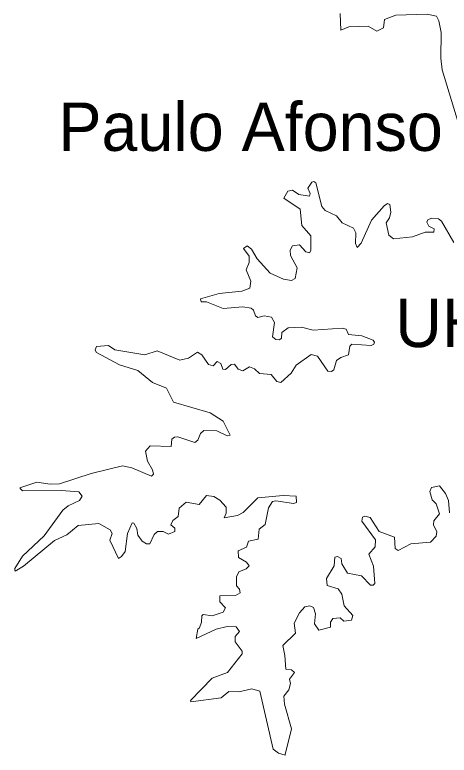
# Model space of a CAD drawing. Extents: x 553962 to 842807, y 8883888 to 9032388.
# Drawn here: x 579268 to 583762, y 8954217 to 8961876 of the extents above; entities that cross this region are included whole.
import ezdxf
from ezdxf.enums import TextEntityAlignment as Align

# ---------------------------------------------------------------- set-up
doc = ezdxf.new("R2010")
doc.units = 0
doc.header["$LTSCALE"] = 200
doc.layers.add('25', color=7, linetype='Continuous', lineweight=13)
doc.layers.add('41', color=7, linetype='Continuous')
doc.layers.add('42', color=7, linetype='Continuous')

msp = doc.modelspace()

# ---------------------------------------------------------------- linework, layer by layer
at = {"layer": '25'}
for points in [[(583979.3, 8960356.6), (583690.5, 8961308.2), (583675.7, 8961427), (583679.9, 8961694.8), (583656.7, 8961812.9), (583631.9, 8961861.4), (583535.2, 8961883.6), (583208.6, 8961873.1), (583093.8, 8961826.3), (583082.9, 8961741.4), (583013.1, 8961707.5), (582923.6, 8961760.4), (582724.2, 8961752), (582642.1, 8961718.4), (582632.6, 8961889.8)], [(583979.3, 8960356.6), (583690.5, 8961308.2), (583675.7, 8961427), (583679.9, 8961694.8), (583656.7, 8961812.9), (583631.9, 8961861.4), (583535.2, 8961883.6), (583208.6, 8961873.1), (583093.8, 8961826.3), (583082.9, 8961741.4), (583013.1, 8961707.5), (582923.6, 8961760.4), (582724.2, 8961752), (582642.1, 8961718.4), (582632.6, 8961889.8)], [(582299.4, 8960082.5), (582339.6, 8960143.8), (582362.8, 8960152.2), (582381.9, 8960139.6), (582443.6, 8959893.3), (582477.6, 8959853), (582596.3, 8959797.7), (582656.1, 8959725.5), (582771.8, 8959670.2), (582795.6, 8959619.4), (582792, 8959510.9), (582809, 8959470.7), (582851.4, 8959515.1), (582957.8, 8959753.2), (583089.5, 8959901.9), (583125.3, 8959922.9), (583148.8, 8959914.2), (583159.4, 8959833.8), (583144.6, 8959774.5), (583108.6, 8959723.3), (583108.6, 8959723.3), (583138.3, 8959595.9), (583184.5, 8959559.9), (583382, 8959578.8), (583514.4, 8959627.7), (583603.4, 8959628), (583607.5, 8959661.8), (583550.2, 8959691.6), (583531.3, 8959731.8), (583541.6, 8959757), (583580.3, 8959774.3), (583651.7, 8959765.9), (583684, 8959740.2), (583809.5, 8959521.5)], [(582299.4, 8960082.5), (582339.6, 8960143.8), (582362.8, 8960152.2), (582381.9, 8960139.6), (582443.6, 8959893.3), (582477.6, 8959853), (582596.3, 8959797.7), (582656.1, 8959725.5), (582771.8, 8959670.2), (582795.6, 8959619.4), (582792, 8959510.9), (582809, 8959470.7), (582851.4, 8959515.1), (582957.8, 8959753.2), (583089.5, 8959901.9), (583125.3, 8959922.9), (583148.8, 8959914.2), (583159.4, 8959833.8), (583144.6, 8959774.5), (583108.6, 8959723.3), (583108.6, 8959723.3), (583138.3, 8959595.9), (583184.5, 8959559.9), (583382, 8959578.8), (583514.4, 8959627.7), (583603.4, 8959628), (583607.5, 8959661.8), (583550.2, 8959691.6), (583531.3, 8959731.8), (583541.6, 8959757), (583580.3, 8959774.3), (583651.7, 8959765.9), (583684, 8959740.2), (583809.5, 8959521.5)], [(580099.6, 8958407.9), (580098.5, 8958410.3), (580113.2, 8958444.3), (580235.9, 8958453.9), (580303, 8958410.4), (580612.5, 8958359.6), (580740.2, 8958401.9), (580973.9, 8958304.4), (581064.7, 8958323.4), (581156.5, 8958384.9), (581203.2, 8958359.3), (581270.9, 8958257.8), (581319.8, 8958245), (581360.2, 8958291.4), (581400.5, 8958268.1), (581420.4, 8958210.8), (581447.3, 8958208.8), (581504.7, 8958259.6), (581539.6, 8958263.8), (581539.6, 8958263.8), (581578.9, 8958209), (581627.9, 8958191.9), (581696, 8958236.1), (581748.9, 8958212.8), (581799.4, 8958164.3), (581920, 8958154), (581978.5, 8958081.4), (582019.4, 8958072.8), (582127.2, 8958170.8), (582178.1, 8958253.3), (582332.9, 8958361.5), (582401, 8958344.6), (582505.1, 8958189.8), (582543.4, 8958185.4), (582568.8, 8958204.3), (582596.6, 8958300), (582641.2, 8958331.9), (582721.7, 8958357.6), (582732.5, 8958448.5), (582755.7, 8958467.7), (582953.2, 8958455.2), (582983.1, 8958470.1), (582989.4, 8958491.2), (582974.4, 8958510.4), (582859.9, 8958554.9), (582719.7, 8958570.1), (582696.2, 8958625.2), (582656.2, 8958635.6), (582353.6, 8958614.5), (582235.7, 8958646.3), (582095.5, 8958639.9), (582031.7, 8958591.2), (582027, 8958531.6), (582005.7, 8958514.7), (581967.3, 8958516.9), (581933.7, 8958544.9), (581955, 8958692.5), (581922.9, 8958748.3), (581848.8, 8958761), (581780.6, 8958746.3), (581757.5, 8958761.1), (581738.2, 8958822.6), (581712.6, 8958841.7), (581627.9, 8958854.5), (581424.2, 8958839.7), (581251.8, 8958907.5), (581194.6, 8958907.9), (581190.6, 8958937.3), (581381.2, 8958994.6), (581615.1, 8959015.9), (581699.9, 8959047.7), (581708.6, 8959122.1), (581659.8, 8959239), (581692.1, 8959315.5), (581691.6, 8959378.9), (581634.5, 8959460), (581670.4, 8959485.2), (581717.2, 8959451.2), (581774.6, 8959353.5), (581908.3, 8959202.9), (582046.5, 8959141.3), (582129.4, 8959128.6), (582167.3, 8959147.5), (582188.6, 8959260.2), (582118.7, 8959385.4), (582116.5, 8959440.5), (582142.1, 8959487.4), (582214.1, 8959495.9), (582278, 8959423.9), (582316.1, 8959415.5), (582331, 8959439.1), (582330.8, 8959589.7), (582237.6, 8959695.7), (582220.4, 8959865.6), (582050.7, 8959980.4), (582091.2, 8960052.6), (582141.7, 8960063.2), (582208.1, 8960016.5), (582315.9, 8960001.7), (582322.5, 8960029), (582299.4, 8960082.5)], [(580099.6, 8958407.9), (580098.5, 8958410.3), (580113.2, 8958444.3), (580235.9, 8958453.9), (580303, 8958410.4), (580612.5, 8958359.6), (580740.2, 8958401.9), (580973.9, 8958304.4), (581064.7, 8958323.4), (581156.5, 8958384.9), (581203.2, 8958359.3), (581270.9, 8958257.8), (581319.8, 8958245), (581360.2, 8958291.4), (581400.5, 8958268.1), (581420.4, 8958210.8), (581447.3, 8958208.8), (581504.7, 8958259.6), (581539.6, 8958263.8), (581539.6, 8958263.8), (581578.9, 8958209), (581627.9, 8958191.9), (581696, 8958236.1), (581748.9, 8958212.8), (581799.4, 8958164.3), (581920, 8958154), (581978.5, 8958081.4), (582019.4, 8958072.8), (582127.2, 8958170.8), (582178.1, 8958253.3), (582332.9, 8958361.5), (582401, 8958344.6), (582505.1, 8958189.8), (582543.4, 8958185.4), (582568.8, 8958204.3), (582596.6, 8958300), (582641.2, 8958331.9), (582721.7, 8958357.6), (582732.5, 8958448.5), (582755.7, 8958467.7), (582953.2, 8958455.2), (582983.1, 8958470.1), (582989.4, 8958491.2), (582974.4, 8958510.4), (582859.9, 8958554.9), (582719.7, 8958570.1), (582696.2, 8958625.2), (582656.2, 8958635.6), (582353.6, 8958614.5), (582235.7, 8958646.3), (582095.5, 8958639.9), (582031.7, 8958591.2), (582027, 8958531.6), (582005.7, 8958514.7), (581967.3, 8958516.9), (581933.7, 8958544.9), (581955, 8958692.5), (581922.9, 8958748.3), (581848.8, 8958761), (581780.6, 8958746.3), (581757.5, 8958761.1), (581738.2, 8958822.6), (581712.6, 8958841.7), (581627.9, 8958854.5), (581424.2, 8958839.7), (581251.8, 8958907.5), (581194.6, 8958907.9), (581190.6, 8958937.3), (581381.2, 8958994.6), (581615.1, 8959015.9), (581699.9, 8959047.7), (581708.6, 8959122.1), (581659.8, 8959239), (581692.1, 8959315.5), (581691.6, 8959378.9), (581634.5, 8959460), (581670.4, 8959485.2), (581717.2, 8959451.2), (581774.6, 8959353.5), (581908.3, 8959202.9), (582046.5, 8959141.3), (582129.4, 8959128.6), (582167.3, 8959147.5), (582188.6, 8959260.2), (582118.7, 8959385.4), (582116.5, 8959440.5), (582142.1, 8959487.4), (582214.1, 8959495.9), (582278, 8959423.9), (582316.1, 8959415.5), (582331, 8959439.1), (582330.8, 8959589.7), (582237.6, 8959695.7), (582220.4, 8959865.6), (582050.7, 8959980.4), (582091.2, 8960052.6), (582141.7, 8960063.2), (582208.1, 8960016.5), (582315.9, 8960001.7), (582322.5, 8960029), (582299.4, 8960082.5)], [(579330.4, 8956970.9), (579320.1, 8956982.2), (579494.9, 8957040.3), (579635.1, 8957021.3), (579729, 8957025.6), (580056.8, 8957131.9), (580383.3, 8957210.3), (580477.4, 8957190.9), (580682.8, 8957104.2), (580701.6, 8957122.8), (580693.2, 8957169.7), (580640, 8957259.4), (580619.2, 8957363.6), (580667.8, 8957416.2), (580886.3, 8957410), (580890.9, 8957486.6), (580919.1, 8957507.7), (580955.2, 8957509.6), (581130.8, 8957450.5), (581162.8, 8957476.1), (581188.5, 8957544.2), (581224.5, 8957577.8), (581357.9, 8957571.4), (581466.2, 8957520.6), (581496, 8957526.9), (581421.8, 8957673.3), (581289.9, 8957760.6), (580910.1, 8957870.9), (580835.5, 8958013.2), (580692.5, 8958073.2), (580540.2, 8958198), (580349.1, 8958255.5), (580111.4, 8958382.8), (580099.6, 8958407.9)], [(579330.4, 8956970.9), (579320.1, 8956982.2), (579494.9, 8957040.3), (579635.1, 8957021.3), (579729, 8957025.6), (580056.8, 8957131.9), (580383.3, 8957210.3), (580477.4, 8957190.9), (580682.8, 8957104.2), (580701.6, 8957122.8), (580693.2, 8957169.7), (580640, 8957259.4), (580619.2, 8957363.6), (580667.8, 8957416.2), (580886.3, 8957410), (580890.9, 8957486.6), (580919.1, 8957507.7), (580955.2, 8957509.6), (581130.8, 8957450.5), (581162.8, 8957476.1), (581188.5, 8957544.2), (581224.5, 8957577.8), (581357.9, 8957571.4), (581466.2, 8957520.6), (581496, 8957526.9), (581421.8, 8957673.3), (581289.9, 8957760.6), (580910.1, 8957870.9), (580835.5, 8958013.2), (580692.5, 8958073.2), (580540.2, 8958198), (580349.1, 8958255.5), (580111.4, 8958382.8), (580099.6, 8958407.9)], [(583767, 8956723.9), (583756.3, 8956851.3), (583724.4, 8956925.6), (583660.8, 8957002.1), (583580.2, 8956987.2), (583561.1, 8956946.9), (583586.5, 8956859.9), (583628.7, 8956817.4), (583660.7, 8956715.7), (583603.4, 8956642.9), (583599.3, 8956600.4), (583635.2, 8956528.2), (583628.9, 8956482), (583569.2, 8956422.2), (583365.5, 8956403), (583235.8, 8956333.2), (583204.2, 8956354.3), (583197.6, 8956473.1), (583036.3, 8956532.7), (582944.7, 8956675), (582889.9, 8956689.8), (582866.4, 8956681.3), (582857.8, 8956639.1), (583000.1, 8956445.4), (583000.1, 8956445.4), (582995.8, 8956371.3), (582932.2, 8956297.6), (582978.9, 8956171.6), (582991.4, 8955993), (582976.7, 8955976.2), (582947.1, 8955976.2), (582856.3, 8956071.3), (582711.3, 8956099.4), (582652.2, 8956196.2), (582645.2, 8956252.4), (582607.4, 8956273.4), (582579.8, 8956265), (582570.9, 8956175.6), (582492.5, 8956044.1), (582498.8, 8955974.4), (582613.2, 8955937.9), (582649.7, 8955884.6), (582675.3, 8955763.5), (582766.3, 8955661.9), (582751.6, 8955613.2), (582671.6, 8955604.4), (582632.4, 8955638.4), (582558.3, 8955632), (582532.9, 8955594), (582534.7, 8955540.7), (582411.8, 8955511), (582367.2, 8955576.8), (582379.8, 8955678.5), (582358.6, 8955744.6), (582321.7, 8955763.6), (582269.6, 8955750.9), (582214, 8955691.2), (582157.1, 8955581.8), (582171.5, 8955478.9), (582040.1, 8955351.6), (582061.2, 8955249.4), (582072.2, 8955107.3), (582129.2, 8955100.8), (582163, 8955071.2), (582108.2, 8955005.5), (582120.6, 8954960.7), (582103.7, 8954893.1), (582052.8, 8954828.8), (582057, 8954744.1), (582129.2, 8954489.4), (582066.7, 8954223.6)], [(583767, 8956723.9), (583756.3, 8956851.3), (583724.4, 8956925.6), (583660.8, 8957002.1), (583580.2, 8956987.2), (583561.1, 8956946.9), (583586.5, 8956859.9), (583628.7, 8956817.4), (583660.7, 8956715.7), (583603.4, 8956642.9), (583599.3, 8956600.4), (583635.2, 8956528.2), (583628.9, 8956482), (583569.2, 8956422.2), (583365.5, 8956403), (583235.8, 8956333.2), (583204.2, 8956354.3), (583197.6, 8956473.1), (583036.3, 8956532.7), (582944.7, 8956675), (582889.9, 8956689.8), (582866.4, 8956681.3), (582857.8, 8956639.1), (583000.1, 8956445.4), (583000.1, 8956445.4), (582995.8, 8956371.3), (582932.2, 8956297.6), (582978.9, 8956171.6), (582991.4, 8955993), (582976.7, 8955976.2), (582947.1, 8955976.2), (582856.3, 8956071.3), (582711.3, 8956099.4), (582652.2, 8956196.2), (582645.2, 8956252.4), (582607.4, 8956273.4), (582579.8, 8956265), (582570.9, 8956175.6), (582492.5, 8956044.1), (582498.8, 8955974.4), (582613.2, 8955937.9), (582649.7, 8955884.6), (582675.3, 8955763.5), (582766.3, 8955661.9), (582751.6, 8955613.2), (582671.6, 8955604.4), (582632.4, 8955638.4), (582558.3, 8955632), (582532.9, 8955594), (582534.7, 8955540.7), (582411.8, 8955511), (582367.2, 8955576.8), (582379.8, 8955678.5), (582358.6, 8955744.6), (582321.7, 8955763.6), (582269.6, 8955750.9), (582214, 8955691.2), (582157.1, 8955581.8), (582171.5, 8955478.9), (582040.1, 8955351.6), (582061.2, 8955249.4), (582072.2, 8955107.3), (582129.2, 8955100.8), (582163, 8955071.2), (582108.2, 8955005.5), (582120.6, 8954960.7), (582103.7, 8954893.1), (582052.8, 8954828.8), (582057, 8954744.1), (582129.2, 8954489.4), (582066.7, 8954223.6)], [(579269.2, 8956128.5), (579267.5, 8956147.6), (579346.5, 8956275.5), (579569.6, 8956488.2), (579763, 8956751.6), (579818, 8956796.1), (579936.8, 8956853.3), (579964.5, 8956895.9), (579931, 8956942.9), (579750.3, 8956955.4), (579346.5, 8956953.4), (579330.4, 8956970.9)], [(579269.2, 8956128.5), (579267.5, 8956147.6), (579346.5, 8956275.5), (579569.6, 8956488.2), (579763, 8956751.6), (579818, 8956796.1), (579936.8, 8956853.3), (579964.5, 8956895.9), (579931, 8956942.9), (579750.3, 8956955.4), (579346.5, 8956953.4), (579330.4, 8956970.9)], [(581087.4, 8954777.9), (581086.2, 8954783.2), (581309.3, 8955015.9), (581466.6, 8955071.4), (581619.3, 8955264.8), (581619.2, 8955294.3), (581547.2, 8955390.1), (581547.2, 8955446.9), (581591.7, 8955496), (581559.6, 8955544.9), (581466.4, 8955547), (581352.5, 8955521.7), (581145.7, 8955426.2), (581160.6, 8955521.3), (581179.9, 8955534.8), (581200.8, 8955593.5), (581201, 8955657.4), (581215.8, 8955674.4), (581310.1, 8955657.7), (581421.9, 8955695.9), (581449.3, 8955742.7), (581390.1, 8955804.1), (581390.2, 8955865.7), (581551.4, 8955867.9), (581597.9, 8955895.3), (581593.8, 8955933.6), (581560, 8955969.8), (581562.1, 8956061.3), (581585.5, 8956114.1), (581661.8, 8956146.1), (581693.6, 8956177.9), (581665.8, 8956214.1), (581581.2, 8956260.8), (581578.8, 8956332.5), (581666, 8956369.2), (581685.3, 8956432.7), (581787.1, 8956452), (581795.2, 8956554.8), (581857.1, 8956604.5), (581891.2, 8956774.6), (581933.5, 8956840.4), (581969.4, 8956847.3), (582150.4, 8956819.5), (582182.3, 8956832.5), (582180, 8956896), (582043.8, 8956902.2), (581783.2, 8956880.5), (581783.2, 8956880.5), (581630, 8956728.1), (581572.6, 8956696.3), (581434.7, 8956673.2), (581455.8, 8956719.8), (581453.6, 8956783.3), (581388, 8956855.3), (581326.2, 8956893.7), (581251.9, 8956904.3), (581175.2, 8956811), (581041.6, 8956834.2), (580969.4, 8956772.7), (580958.6, 8956687.6), (580901.5, 8956645.2), (580882.6, 8956601.5), (580922.5, 8956566.6), (580922.4, 8956530.5), (580856.8, 8956505.1), (580801.5, 8956530.5), (580744, 8956530.4), (580708.6, 8956501.7), (580663.4, 8956403.2), (580631.7, 8956403.2), (580586.8, 8956433.1), (580540.2, 8956494.7), (580531.6, 8956562.6), (580499.8, 8956617.5), (580482.8, 8956619.5), (580431.9, 8956511.2), (580408.5, 8956324.5), (580372.3, 8956271.5), (580340.8, 8956252.5), (580251.5, 8956443.2), (580274.6, 8956509.1), (580253.4, 8956549.5), (580136.6, 8956613.3), (579924, 8956592), (579805, 8956498.6), (579677.6, 8956436.9), (579359.2, 8956171.6), (579269.9, 8956121.1), (579269.2, 8956128.5)], [(581087.4, 8954777.9), (581086.2, 8954783.2), (581309.3, 8955015.9), (581466.6, 8955071.4), (581619.3, 8955264.8), (581619.2, 8955294.3), (581547.2, 8955390.1), (581547.2, 8955446.9), (581591.7, 8955496), (581559.6, 8955544.9), (581466.4, 8955547), (581352.5, 8955521.7), (581145.7, 8955426.2), (581160.6, 8955521.3), (581179.9, 8955534.8), (581200.8, 8955593.5), (581201, 8955657.4), (581215.8, 8955674.4), (581310.1, 8955657.7), (581421.9, 8955695.9), (581449.3, 8955742.7), (581390.1, 8955804.1), (581390.2, 8955865.7), (581551.4, 8955867.9), (581597.9, 8955895.3), (581593.8, 8955933.6), (581560, 8955969.8), (581562.1, 8956061.3), (581585.5, 8956114.1), (581661.8, 8956146.1), (581693.6, 8956177.9), (581665.8, 8956214.1), (581581.2, 8956260.8), (581578.8, 8956332.5), (581666, 8956369.2), (581685.3, 8956432.7), (581787.1, 8956452), (581795.2, 8956554.8), (581857.1, 8956604.5), (581891.2, 8956774.6), (581933.5, 8956840.4), (581969.4, 8956847.3), (582150.4, 8956819.5), (582182.3, 8956832.5), (582180, 8956896), (582043.8, 8956902.2), (581783.2, 8956880.5), (581783.2, 8956880.5), (581630, 8956728.1), (581572.6, 8956696.3), (581434.7, 8956673.2), (581455.8, 8956719.8), (581453.6, 8956783.3), (581388, 8956855.3), (581326.2, 8956893.7), (581251.9, 8956904.3), (581175.2, 8956811), (581041.6, 8956834.2), (580969.4, 8956772.7), (580958.6, 8956687.6), (580901.5, 8956645.2), (580882.6, 8956601.5), (580922.5, 8956566.6), (580922.4, 8956530.5), (580856.8, 8956505.1), (580801.5, 8956530.5), (580744, 8956530.4), (580708.6, 8956501.7), (580663.4, 8956403.2), (580631.7, 8956403.2), (580586.8, 8956433.1), (580540.2, 8956494.7), (580531.6, 8956562.6), (580499.8, 8956617.5), (580482.8, 8956619.5), (580431.9, 8956511.2), (580408.5, 8956324.5), (580372.3, 8956271.5), (580340.8, 8956252.5), (580251.5, 8956443.2), (580274.6, 8956509.1), (580253.4, 8956549.5), (580136.6, 8956613.3), (579924, 8956592), (579805, 8956498.6), (579677.6, 8956436.9), (579359.2, 8956171.6), (579269.9, 8956121.1), (579269.2, 8956128.5)], [(582066.7, 8954223.6), (582065.2, 8954217.4), (581995.8, 8954238.9), (581939.2, 8954279.2), (581803.6, 8954880.3), (581719.8, 8954905.5), (581585.7, 8954873.7), (581483.7, 8954877.8), (581402.7, 8954812.1), (581089.5, 8954768.8), (581087.4, 8954777.9)], [(582066.7, 8954223.6), (582065.2, 8954217.4), (581995.8, 8954238.9), (581939.2, 8954279.2), (581803.6, 8954880.3), (581719.8, 8954905.5), (581585.7, 8954873.7), (581483.7, 8954877.8), (581402.7, 8954812.1), (581089.5, 8954768.8), (581087.4, 8954777.9)]]:
    msp.add_lwpolyline(points, dxfattribs=at)

# ---------------------------------------------------------------- texts
at = {"layer": '41'}
msp.add_text('Paulo Afonso', height=500, dxfattribs=at).set_placement((581707.6, 8960468.8), align=Align.CENTER)
at = {"layer": '42'}
msp.add_text('UHE PA IV', height=500, dxfattribs=at).set_placement((584857.3, 8958438.7), align=Align.CENTER)

doc.saveas('drawing.dxf')
